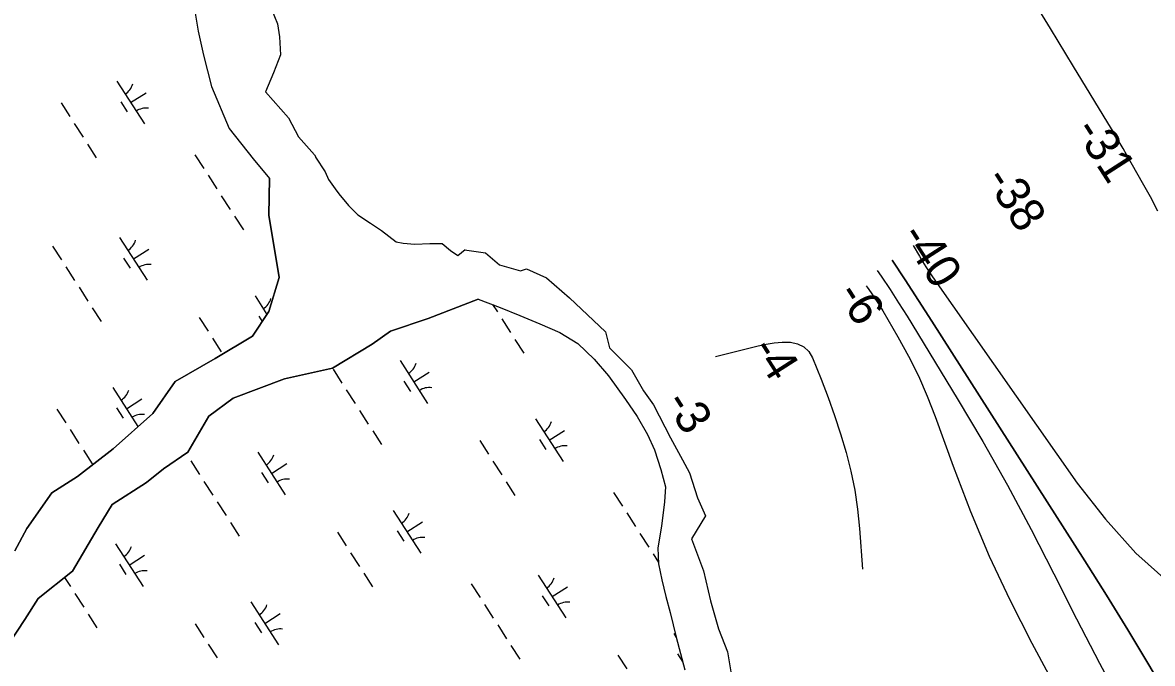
# Model space of a CAD drawing. Extents: x 3937982 to 3958556, y 219448 to 241894.
# Drawn here: x 3949325 to 3950436, y 225295 to 225925 of the extents above; entities that cross this region are included whole.
import ezdxf

# ---------------------------------------------------------------- set-up
doc = ezdxf.new("R2010")
doc.units = 0
for name, color, linetype in [('V-RIVR-EDGE', 7, 'Continuous'), ('V-RIVR-RANG', 7, 'Continuous'), ('V-TOPO-DPTH', 7, 'Continuous'), ('V-TOPO-MINR', 7, 'Continuous'), ('V-TOPO-SHOR', 7, 'Continuous'), ('V-WETL-SWMP', 7, 'Continuous')]:
    doc.layers.add(name, color=color, linetype=linetype)

msp = doc.modelspace()

# ---------------------------------------------------------------- linework, layer by layer
at = {"layer": 'V-RIVR-EDGE'}
for points in [[(3949569.8, 225938.416), (3949575.698, 225923.672), (3949577.664, 225910.895), (3949578.646, 225893.203), (3949571.766, 225875.51), (3949563.903, 225856.835), (3949586.51, 225831.28), (3949596.339, 225812.605), (3949612.065, 225794.913), (3949613.381, 225792.774)], [(3949613.047, 225792.833), (3949622.575, 225778.392), (3949625.85, 225770.799), (3949632.252, 225761.569), (3949635.974, 225756.656), (3949645.353, 225745.341), (3949654.584, 225735.962), (3949666.941, 225727.773), (3949677.958, 225720.478), (3949692.25, 225709.61), (3949699.248, 225708.27), (3949710.562, 225707.079), (3949725.45, 225707.823), (3949737.509, 225707.972), (3949745.698, 225700.826), (3949752.993, 225696.211), (3949759.99, 225701.868)], [(3949759.499, 225701.538), (3949780.14, 225698.589), (3949793.901, 225686.794), (3949814.541, 225680.897), (3949820.439, 225682.863), (3949840.097, 225674.017), (3949862.703, 225654.359), (3949898.088, 225620.94), (3949902.019, 225605.214), (3949923.643, 225583.59), (3949935.438, 225562.95), (3949945.267, 225549.189), (3949961.976, 225516.754), (3949973.771, 225495.13), (3949980.651, 225482.352), (3949988.514, 225457.78), (3949996.377, 225440.088), (3949982.617, 225417.481), (3949985.565, 225409.618), (3949994.411, 225386.028), (3950001.292, 225356.541), (3950009.155, 225329.02), (3950018.001, 225306.414), (3950031.761, 225223.851)]]:
    msp.add_lwpolyline(points, dxfattribs=at)
at = {"layer": 'V-TOPO-DPTH'}
for points in [[(3950441.107, 225739.5), (3950433.719, 225753.653), (3950426.039, 225767.661), (3950410.625, 225794.786), (3950406.881, 225801.303), (3950403.098, 225807.796), (3950399.254, 225814.254), (3950395.37, 225820.689), (3950357.961, 225882.016), (3950335.35, 225919.101), (3950312.75, 225956.193)], [(3950200.524, 225705.91), (3950206.578, 225695.373), (3950209.659, 225690.175), (3950212.831, 225685.035), (3950216.14, 225679.982), (3950219.54, 225674.988), (3950361.634, 225472.19), (3950389.411, 225436.702), (3950419.41, 225403.441), (3950452.743, 225373.523)], [(3951131.518, 224213.954), (3950902.17, 224513.573), (3950592.78, 225014.631), (3950589.938, 225017.696), (3950532.216, 225120.153), (3950512.481, 225155.009), (3950492.647, 225189.808), (3950472.664, 225224.522), (3950452.583, 225259.179), (3950432.218, 225293.666), (3950411.575, 225327.984), (3950390.515, 225362.047), (3950369.176, 225395.94), (3950218.895, 225631.439), (3950205.782, 225651.837), (3950192.58, 225672.175), (3950179.783, 225691.607)], [(3951680.229, 223402.255), (3951578.518, 223569.264), (3951533.246, 223643.597), (3951487.972, 223717.928), (3951442.696, 223792.258), (3951397.418, 223866.587), (3950902.17, 224513.573), (3950592.78, 225014.631), (3950589.938, 225017.696), (3950532.216, 225120.153), (3950512.481, 225155.009), (3950492.647, 225189.808), (3950472.664, 225224.522), (3950452.583, 225259.179), (3950432.218, 225293.666), (3950411.575, 225327.984), (3950390.515, 225362.047), (3950369.176, 225395.94), (3950218.895, 225631.439), (3950205.782, 225651.837), (3950192.58, 225672.175), (3950179.783, 225691.607)], [(3950154.242, 225666.143), (3950155.218, 225664.85), (3950159.295, 225659.241), (3950163.235, 225653.541), (3950166.968, 225647.703), (3950170.564, 225641.773), (3950185.469, 225616.173), (3950195.874, 225597.123), (3950205.566, 225577.74), (3950214.186, 225557.858), (3950222.093, 225537.642), (3950239.689, 225488.764), (3950256.82, 225444.288), (3950275.232, 225400.383), (3950295.567, 225357.335), (3950317.183, 225314.858), (3950518.206, 224940.562)]]:
    msp.add_lwpolyline(points, dxfattribs=at)
at = {"layer": 'V-TOPO-MINR'}
for points in [[(3950441.107, 225739.5), (3950433.719, 225753.653), (3950426.039, 225767.661), (3950410.625, 225794.786), (3950406.881, 225801.303), (3950403.098, 225807.796), (3950399.254, 225814.254), (3950395.37, 225820.689), (3950357.961, 225882.016), (3950335.35, 225919.101), (3950312.75, 225956.193)], [(3950200.524, 225705.91), (3950206.578, 225695.373), (3950209.659, 225690.175), (3950212.831, 225685.035), (3950216.14, 225679.982), (3950219.54, 225674.988), (3950361.634, 225472.19), (3950389.411, 225436.702), (3950419.41, 225403.441), (3950452.743, 225373.523)], [(3950179.783, 225691.607), (3950192.58, 225672.175), (3950205.782, 225651.837), (3950218.895, 225631.439), (3950369.176, 225395.94), (3950390.515, 225362.047), (3950411.575, 225327.984), (3950432.218, 225293.666), (3950452.583, 225259.179), (3950472.664, 225224.522), (3950492.647, 225189.808), (3950512.481, 225155.009), (3950532.216, 225120.153), (3950589.938, 225017.696), (3950592.78, 225014.631), (3950902.17, 224513.573), (3951397.418, 223866.587), (3951442.696, 223792.258), (3951487.972, 223717.928), (3951533.246, 223643.597), (3951578.518, 223569.264), (3951680.229, 223402.255)], [(3950165.159, 225681.309), (3950169.051, 225675.688), (3950177.749, 225662.755), (3950186.183, 225649.647), (3950194.44, 225636.423), (3950243.826, 225555.508), (3950268.931, 225513.1), (3950293.263, 225470.266), (3950316.432, 225426.793), (3950338.828, 225382.893), (3950360.999, 225338.862), (3950383.649, 225295.084), (3950407.015, 225251.683), (3950430.858, 225208.535), (3950553.653, 224990.574), (3950558.289, 224985.474), (3950786.467, 224611.132), (3950993.17, 224313.696), (3950995.512, 224310.763), (3951582.745, 223493.719), (3951602.364, 223461.504), (3951621.927, 223429.256), (3951641.408, 223396.958), (3951649.976, 223382.696)], [(3950154.242, 225666.143), (3950155.218, 225664.85), (3950159.295, 225659.241), (3950163.235, 225653.541), (3950166.968, 225647.703), (3950170.564, 225641.773), (3950185.469, 225616.173), (3950195.874, 225597.123), (3950205.566, 225577.74), (3950214.186, 225557.858), (3950222.093, 225537.642), (3950239.689, 225488.764), (3950256.82, 225444.288), (3950275.232, 225400.383), (3950295.567, 225357.335), (3950317.183, 225314.858), (3950518.206, 224940.562)], [(3950006.174, 225596.828), (3950048.17, 225607.387), (3950055.98, 225609.006), (3950063.837, 225610.185), (3950071.765, 225610.703), (3950079.74, 225610.781), (3950086.835, 225609.22), (3950093.01, 225606.348), (3950097.803, 225601.512), (3950101.675, 225595.365), (3950110.003, 225574.377), (3950116.756, 225556.577), (3950123.146, 225538.654), (3950128.991, 225520.546), (3950134.473, 225502.315), (3950139.103, 225483.889), (3950142.969, 225465.327), (3950145.686, 225446.564), (3950147.639, 225427.666), (3950150.524, 225387.764)]]:
    msp.add_lwpolyline(points, dxfattribs=at)
at = {"layer": 'V-TOPO-SHOR'}
for points in [[(3949317.277, 225405.801), (3949329.229, 225427.614), (3949353.787, 225462.791), (3949379.061, 225478.642), (3949413.931, 225506.026), (3949452.986, 225540.682), (3949475.149, 225572.22), (3949514.276, 225594.797), (3949550.991, 225616.755), (3949567.156, 225641.01), (3949577.228, 225674.288), (3949567.203, 225735.836), (3949567.713, 225771.615)], [(3949772.935, 225653.249), (3949723.627, 225634.075), (3949686.857, 225621.781), (3949668.812, 225608.991), (3949629.694, 225585.206), (3949582.645, 225574.663), (3949532.02, 225555.641), (3949507.967, 225537.985), (3949487.636, 225502.835), (3949463.572, 225486.386), (3949446.74, 225472.998), (3949413.046, 225451.058), (3949399.285, 225428.63), (3949374.171, 225385.6), (3949340.506, 225358.826), (3949327.337, 225338.213), (3949305.188, 225304.865)]]:
    msp.add_lwpolyline(points, dxfattribs=at)
at = {"layer": 'V-WETL-SWMP'}
for p, q in [((3949493.076, 225944.178), (3949497.702, 225916.734)), ((3949497.702, 225916.734), (3949502.991, 225893.071)), ((3949502.991, 225893.071), (3949510.727, 225862.211)), ((3949417.708, 225867.426), (3949444.77, 225825.383)), ((3949510.727, 225862.211), (3949528.14, 225820.762)), ((3949431.239, 225846.404), (3949446.374, 225856.147)), ((3949362.842, 225846.029), (3949371.502, 225832.575)), ((3949421.504, 225847.274), (3949427.999, 225837.183)), ((3949375.832, 225825.848), (3949384.491, 225812.394)), ((3949528.14, 225820.762), (3949551.735, 225790.956)), ((3949388.821, 225805.667), (3949397.481, 225792.214)), ((3949494.409, 225795.141), (3949503.068, 225781.687)), ((3949551.735, 225790.956), (3949567.713, 225771.614)), ((3949507.398, 225774.96), (3949516.058, 225761.506)), ((3949567.713, 225771.614), (3949567.203, 225735.836)), ((3949520.388, 225754.779), (3949529.048, 225741.326)), ((3949533.378, 225734.599), (3949542.038, 225721.145)), ((3949567.203, 225735.836), (3949577.228, 225674.288)), ((3949354.541, 225705.111), (3949363.201, 225691.658)), ((3949420.406, 225713.706), (3949447.469, 225671.663)), ((3949424.202, 225693.554), (3949430.697, 225683.464)), ((3949433.937, 225692.685), (3949449.073, 225702.427)), ((3949367.531, 225684.931), (3949376.191, 225671.477)), ((3949577.228, 225674.288), (3949567.155, 225641.01)), ((3949380.521, 225664.75), (3949389.181, 225651.296)), ((3949553.536, 225656.408), (3949565.269, 225638.18)), ((3949723.628, 225634.076), (3949772.934, 225653.248)), ((3949772.934, 225653.248), (3949794.617, 225644.791)), ((3949393.511, 225644.569), (3949402.171, 225631.115)), ((3949567.155, 225641.01), (3949550.99, 225616.756)), ((3949787.121, 225647.715), (3949791.754, 225640.518)), ((3949794.617, 225644.791), (3949813.893, 225637.006)), ((3949498.669, 225635.011), (3949507.329, 225621.557)), ((3949557.332, 225636.255), (3949560.601, 225631.176)), ((3949686.857, 225621.781), (3949723.628, 225634.076)), ((3949796.083, 225633.791), (3949804.743, 225620.337)), ((3949813.893, 225637.006), (3949833.514, 225628.879)), ((3949833.514, 225628.879), (3949853.137, 225620.41)), ((3949550.99, 225616.756), (3949514.276, 225594.797)), ((3949668.813, 225608.991), (3949686.857, 225621.781)), ((3949853.137, 225620.41), (3949870.714, 225609.524)), ((3949511.659, 225614.83), (3949520.319, 225601.376)), ((3949629.693, 225585.206), (3949668.813, 225608.991)), ((3949809.073, 225613.61), (3949817.733, 225600.156)), ((3949870.714, 225609.524), (3949886.944, 225594.167)), ((3949514.276, 225594.797), (3949475.149, 225572.22)), ((3949886.944, 225594.167), (3949901.119, 225577.767)), ((3949582.644, 225574.663), (3949629.693, 225585.206)), ((3949630.236, 225584.123), (3949638.896, 225570.669)), ((3949696.101, 225592.718), (3949723.164, 225550.674)), ((3949475.149, 225572.22), (3949452.987, 225540.682)), ((3949532.021, 225555.642), (3949582.644, 225574.663)), ((3949699.897, 225572.565), (3949706.392, 225562.475)), ((3949709.633, 225571.696), (3949724.768, 225581.438)), ((3949901.119, 225577.767), (3949917.739, 225554.514)), ((3949413.668, 225566.378), (3949438.489, 225527.817)), ((3949643.226, 225563.942), (3949651.886, 225550.488)), ((3949427.199, 225545.357), (3949442.335, 225555.099)), ((3949507.966, 225537.985), (3949532.021, 225555.642)), ((3949917.739, 225554.514), (3949929.169, 225537.754)), ((3949358.802, 225544.981), (3949367.462, 225531.527)), ((3949452.987, 225540.682), (3949413.931, 225506.026)), ((3949417.464, 225546.226), (3949423.959, 225536.135)), ((3949487.636, 225502.835), (3949507.966, 225537.985)), ((3949656.216, 225543.761), (3949664.876, 225530.307)), ((3949929.169, 225537.754), (3949939.232, 225519.957)), ((3949829.231, 225535.419), (3949856.293, 225493.376)), ((3949371.792, 225524.8), (3949380.452, 225511.347)), ((3949669.206, 225523.58), (3949677.866, 225510.127)), ((3949833.027, 225515.267), (3949839.522, 225505.176)), ((3949842.762, 225514.397), (3949857.897, 225524.14)), ((3949939.232, 225519.957), (3949946.188, 225504.888)), ((3949413.931, 225506.026), (3949379.061, 225478.642)), ((3949384.782, 225504.62), (3949393.442, 225491.166)), ((3949774.365, 225514.022), (3949783.025, 225500.568)), ((3949946.188, 225504.888), (3949952.482, 225485.695)), ((3949463.573, 225486.386), (3949487.636, 225502.835)), ((3949490.369, 225494.093), (3949499.029, 225480.639)), ((3949556.234, 225502.688), (3949583.296, 225460.645)), ((3949787.354, 225493.841), (3949796.014, 225480.387)), ((3949446.74, 225472.999), (3949463.573, 225486.386)), ((3949560.03, 225482.536), (3949566.525, 225472.445)), ((3949569.765, 225481.666), (3949584.901, 225491.409)), ((3949952.482, 225485.695), (3949957.047, 225468.552)), ((3949379.061, 225478.642), (3949353.787, 225462.79)), ((3949413.046, 225451.058), (3949446.74, 225472.999)), ((3949503.359, 225473.912), (3949512.019, 225460.459)), ((3949800.344, 225473.66), (3949809.004, 225460.207)), ((3949353.787, 225462.79), (3949329.23, 225427.615)), ((3949905.932, 225463.134), (3949914.591, 225449.68)), ((3949957.047, 225468.552), (3949956.103, 225453.781)), ((3949399.286, 225428.63), (3949413.046, 225451.058)), ((3949516.349, 225453.732), (3949525.009, 225440.278)), ((3949956.103, 225453.781), (3949953.152, 225430.069)), ((3949689.363, 225445.389), (3949716.426, 225403.346)), ((3949918.921, 225442.953), (3949927.581, 225429.499)), ((3949329.23, 225427.615), (3949317.278, 225405.801)), ((3949374.171, 225385.6), (3949399.286, 225428.63)), ((3949529.339, 225433.551), (3949537.999, 225420.097)), ((3949702.895, 225424.368), (3949718.03, 225434.11)), ((3949953.152, 225430.069), (3949949.5, 225408.757)), ((3949634.497, 225423.992), (3949643.157, 225410.539)), ((3949693.159, 225425.237), (3949699.654, 225415.147)), ((3949931.911, 225422.772), (3949940.571, 225409.319)), ((3949416.367, 225412.659), (3949443.429, 225370.615)), ((3949949.5, 225408.757), (3949950.279, 225392.966)), ((3949429.898, 225391.637), (3949445.034, 225401.379)), ((3949647.487, 225403.812), (3949656.147, 225390.358)), ((3949944.901, 225402.592), (3949950.211, 225394.342)), ((3949950.279, 225392.966), (3949953.462, 225377.188)), ((3949340.505, 225358.827), (3949374.171, 225385.6)), ((3949420.163, 225392.506), (3949426.658, 225382.416)), ((3949660.477, 225383.631), (3949669.137, 225370.177)), ((3949366.376, 225379.401), (3949372.152, 225370.429)), ((3949766.064, 225373.104), (3949774.724, 225359.651)), ((3949831.929, 225381.699), (3949858.992, 225339.656)), ((3949953.462, 225377.188), (3949957.336, 225360.728)), ((3949376.482, 225363.702), (3949385.142, 225350.248)), ((3949835.725, 225361.547), (3949842.22, 225351.456)), ((3949845.46, 225360.678), (3949860.596, 225370.42)), ((3949957.336, 225360.728), (3949961.55, 225344.956)), ((3949327.338, 225338.214), (3949340.505, 225358.827)), ((3949549.496, 225355.36), (3949576.558, 225313.317)), ((3949779.054, 225352.924), (3949787.714, 225339.47)), ((3949305.187, 225304.865), (3949327.338, 225338.214)), ((3949389.472, 225343.521), (3949398.132, 225330.068)), ((3949563.027, 225334.338), (3949578.163, 225344.081)), ((3949961.55, 225344.956), (3949967.53, 225320.61)), ((3949494.63, 225333.963), (3949503.29, 225320.509)), ((3949553.292, 225335.208), (3949559.787, 225325.117)), ((3949792.044, 225332.743), (3949800.704, 225319.289)), ((3949965.058, 225324.401), (3949967.552, 225320.527)), ((3949967.53, 225320.61), (3949975.959, 225288.724)), ((3949507.62, 225313.782), (3949516.28, 225300.328)), ((3949805.034, 225312.562), (3949813.694, 225299.108)), ((3949968.854, 225304.248), (3949973.946, 225296.338)), ((3949910.192, 225303.004), (3949918.852, 225289.55))]:
    msp.add_line(p, q, dxfattribs=at)
for centre, start, end in [((3949416.488, 225869.759), 301.99668, 343.540338), ((3949446.388, 225823.307), 81.996677, 123.540335), ((3949419.187, 225716.039), 301.99668, 343.540338), ((3949449.087, 225669.587), 81.996677, 123.540335), ((3949552.316, 225658.74), 301.99668, 343.540338), ((3949694.882, 225595.05), 301.99668, 343.540338), ((3949412.449, 225568.711), 301.99668, 343.540338), ((3949724.782, 225548.599), 81.996677, 123.540335), ((3949442.349, 225522.259), 81.996677, 123.540335), ((3949828.011, 225537.752), 301.99668, 343.540338), ((3949857.911, 225491.3), 81.996677, 123.540335), ((3949555.015, 225505.021), 301.99668, 343.540338), ((3949584.915, 225458.569), 81.996677, 123.540335), ((3949688.144, 225447.722), 301.99668, 343.540338), ((3949718.044, 225401.27), 81.996677, 123.540335), ((3949415.148, 225414.991), 301.99668, 343.540338), ((3949445.048, 225368.539), 81.996677, 123.540335), ((3949830.71, 225384.032), 301.99668, 343.540338), ((3949548.277, 225357.693), 301.99668, 343.540338), ((3949860.61, 225337.58), 81.996677, 123.540335), ((3949578.177, 225311.241), 81.996677, 123.540335)]:
    msp.add_arc(centre, 17.623, start, end, dxfattribs=at)

# ---------------------------------------------------------------- texts
at = {"layer": 'V-RIVR-RANG'}
for s, rotation, p in [('-31', 302.735444, (3950358.077, 225819.269)), ('-38', 302.735444, (3950270.148, 225771.121)), ('-40', 302.735444, (3950187.321, 225715.592)), ('-6', 302.598326, (3950124.462, 225658.079)), ('-4', 302.598326, (3950040.416, 225603.892)), ('-3', 302.598326, (3949955.375, 225551.26))]:
    msp.add_text(s, height=33.5, rotation=rotation, dxfattribs=at).set_placement(p)

doc.saveas('drawing.dxf')
